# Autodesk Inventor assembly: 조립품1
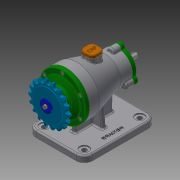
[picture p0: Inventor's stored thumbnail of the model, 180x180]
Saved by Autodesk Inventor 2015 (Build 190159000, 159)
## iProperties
Created: 2021-10
Part Number: 조립품1
Document SubType Name: 용접물
Designer: pc-04
Weld Material: 알루미늄 6061, 용접
Author: pc-04
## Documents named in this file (16)
- C:\Users\pc-04\Desktop\711006V1010\조립품1.iam
- C:\Users\pc-04\Desktop\711006V1010\본체.ipt
- C:\Users\pc-04\Desktop\711006V1010\뒤커버.ipt
- C:\Users\pc-04\Desktop\711006V1010\베어링 6200.ipt
- C:\Users\pc-04\Desktop\711006V1010\오일 실 10x20x7.ipt
- C:\Users\pc-04\Desktop\711006V1010\축.ipt
- C:\Users\pc-04\Desktop\711006V1010\앞커버.ipt
- C:\Users\pc-04\Desktop\711006V1010\베어링 6203.ipt
- C:\Users\pc-04\Desktop\711006V1010\오일 실 17x30x8.ipt
- C:\Users\pc-04\Desktop\711006V1010\키 5x5.ipt
- 키 5 x 5.ipt
- C:\Users\pc-04\Desktop\711006V1010\스프로킷.ipt
- C:\Users\pc-04\Desktop\711006V1010\와셔.ipt
- C:\Users\pc-04\Desktop\711006V1010\볼트 M4.ipt
- 볼트 M4 x 12.ipt
- C:\Users\pc-04\Desktop\711006V1010\마개.ipt
